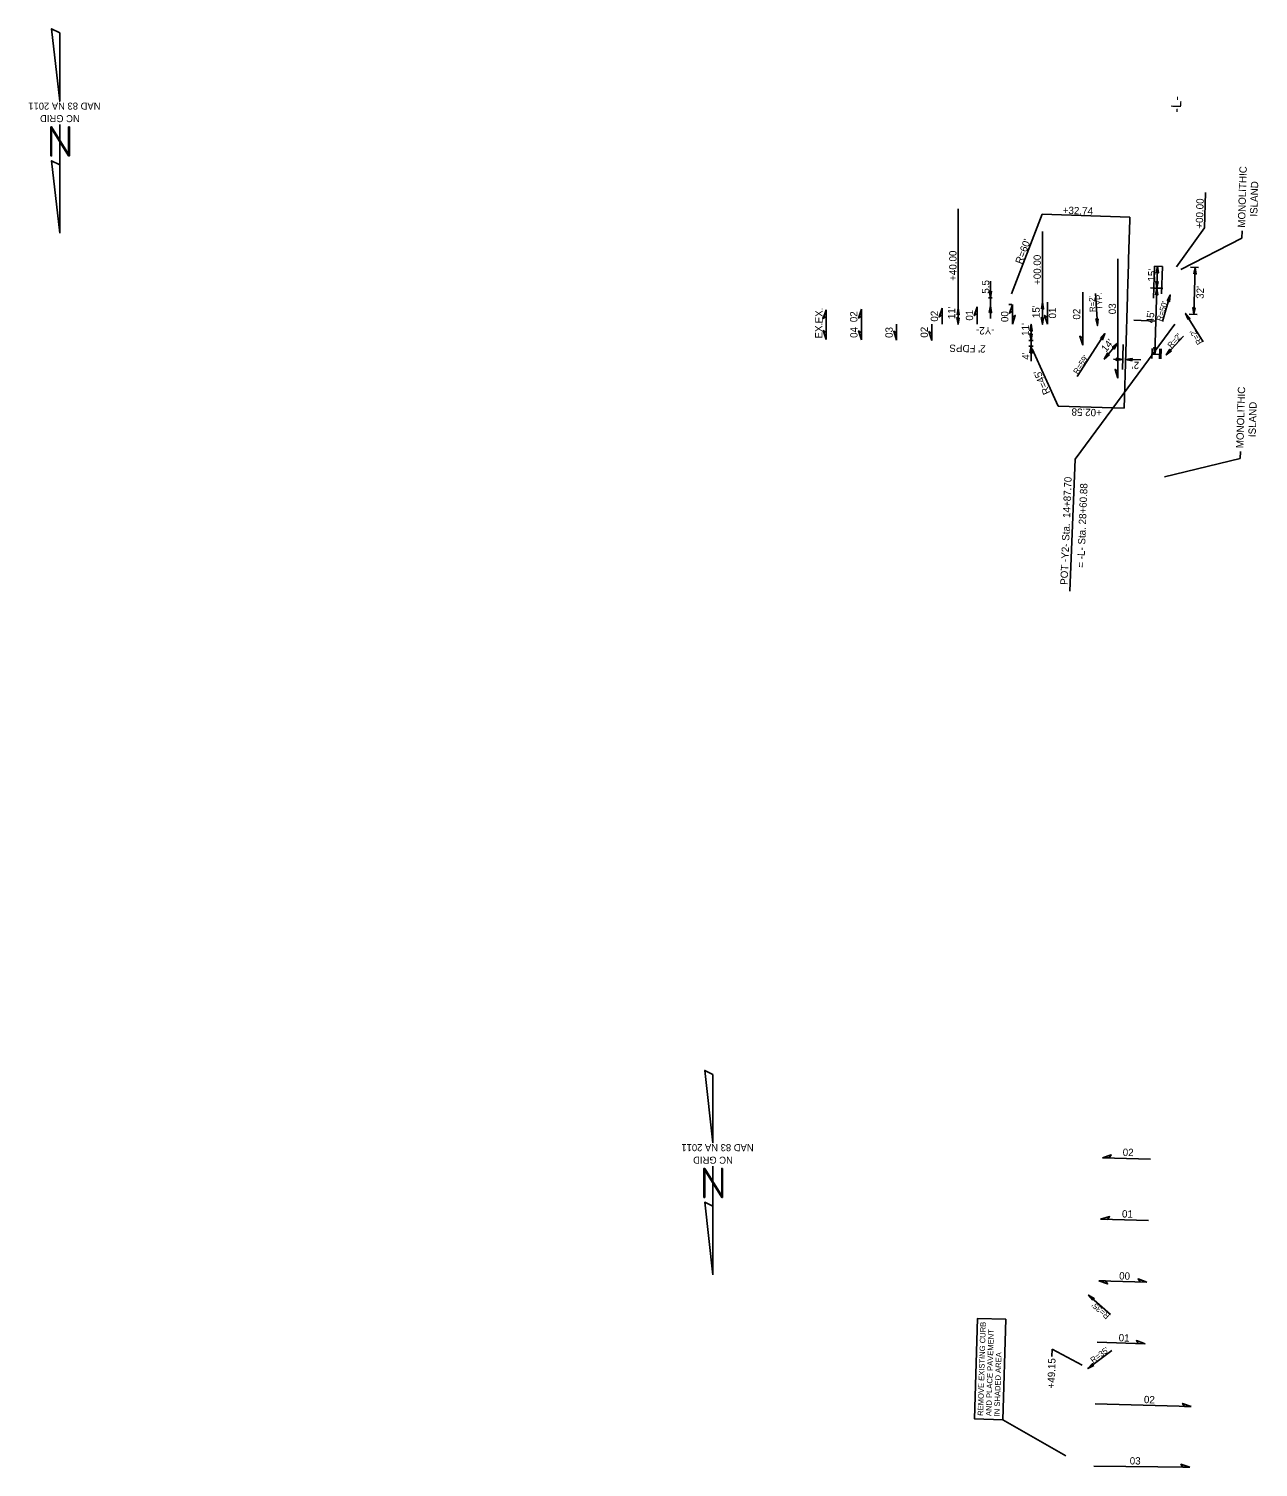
# Model space of a CAD drawing. Extents: x 2096941 to 2098098, y 685096 to 689626.
# Drawn here: x 2096941 to 2097780, y 686100 to 687081 of the extents above; entities that cross this region are included whole.
import ezdxf

# ---------------------------------------------------------------- set-up
doc = ezdxf.new("R2010")
doc.units = 0
for name, color, linetype in [('Default', 7, 'Continuous'), ('Prop Dimension', 7, 'Continuous'), ('Prop Dimension Text', 7, 'Continuous'), ('Prop Horizontal Alignment Direction Label', 7, 'Continuous'), ('Prop Horizontal Alignment Station Label', 7, 'Continuous'), ('Prop Lane Lines', 7, 'Continuous'), ('Prop Superelevation  Arrow CELL', 7, 'Continuous'), ('Prop Superelevation Label', 7, 'Continuous'), ('Prop Terminator CELL', 7, 'Continuous'), ('Scratch_Level_3', 7, 'Continuous')]:
    doc.layers.add(name, color=color, linetype=linetype)

msp = doc.modelspace()

# ---------------------------------------------------------------- linework, layer by layer
at = {"layer": 'Default'}
for p, q in [((2096961.91, 687011.63), (2096961.91, 687011.63)), ((2097407.47, 686301.09), (2097407.47, 686301.09))]:
    msp.add_line(p, q, dxfattribs=at)
for points in [[(2096962.03, 687078.47), (2096956.53, 687081.2), (2096962.03, 687031.81)], [(2096968.61, 687014.24), (2096968.06, 687014.24), (2096968.06, 686995.58), (2096956.53, 687014.24), (2096955.98, 687014.24), (2096955.98, 686994.49), (2096956.53, 686994.49), (2096956.53, 687013.15), (2096968.06, 686994.49), (2096968.61, 686994.49)], [(2096962.03, 686941.8), (2096962.03, 686988.46), (2096956.53, 686991.21)], [(2097407.59, 686367.93), (2097402.09, 686370.66), (2097407.59, 686321.27)], [(2097414.17, 686303.7), (2097413.62, 686303.7), (2097413.62, 686285.04), (2097402.09, 686303.7), (2097401.54, 686303.7), (2097401.54, 686283.95), (2097402.09, 686283.95), (2097402.09, 686302.61), (2097413.62, 686283.95), (2097414.17, 686283.95)], [(2097407.59, 686231.26), (2097407.59, 686277.92), (2097402.09, 686280.67)]]:
    msp.add_lwpolyline(points, close=True, dxfattribs=at)
for points in [[(2096962.03, 686988.46), (2096962.03, 687015.9)], [(2097407.59, 686277.92), (2097407.59, 686305.36)]]:
    msp.add_lwpolyline(points, dxfattribs=at)
at = {"layer": 'Prop Dimension'}
for p, q in [((2097743.02, 686945.33), (2097743.72, 686969.49)), ((2097632.18, 686954.62), (2097611.37, 686900.49)), ((2097692.15, 686952.6), (2097632.18, 686954.62)), ((2097723.82, 686918.76), (2097743.02, 686945.33)), ((2097726.93, 686917), (2097768.51, 686938.38)), ((2097768.51, 686938.38), (2097768.66, 686943.38)), ((2097574.92, 686933.26), (2097574.93, 686897.34)), ((2097632.46, 686930.52), (2097632.47, 686894.61)), ((2097714.33, 686919.12), (2097709, 686919.28)), ((2097710.41, 686904.27), (2097710.84, 686919.22)), ((2097733.37, 686918.52), (2097738.92, 686918.36)), ((2097735.76, 686886.46), (2097736.69, 686918.43)), ((2097596.95, 686909.04), (2097596.96, 686883.63)), ((2097598.15, 686897.7), (2097595.73, 686897.7)), ((2097669.91, 686879.42), (2097668.74, 686900.67)), ((2097713.75, 686904.14), (2097708.43, 686904.35)), ((2097709.1, 686859.23), (2097710.41, 686904.27)), ((2097714.3, 686881.62), (2097719.66, 686899.59)), ((2097574.93, 686890.62), (2097574.93, 686879.62)), ((2097611.64, 686893.05), (2097609.43, 686893.05)), ((2097632.49, 686894.5), (2097632.49, 686879.47)), ((2097742.16, 686867.66), (2097730.11, 686887.07)), ((2097732.44, 686886.55), (2097737.99, 686886.39)), ((2097624.68, 686879.63), (2097624.69, 686854.52)), ((2097626.05, 686868.63), (2097623.09, 686868.63)), ((2097656.07, 686843.89), (2097675.12, 686873.29)), ((2097683.59, 686866.69), (2097674.64, 686855.92)), ((2097687, 686848.84), (2097687.49, 686865.8)), ((2097717.4, 686859.21), (2097728.78, 686871.61)), ((2097626.05, 686864.63), (2097623.09, 686864.63)), ((2097643.25, 686823.64), (2097625.51, 686862.81)), ((2097712.49, 686859.1), (2097707.16, 686859.3)), ((2097687.2, 686855.65), (2097680.86, 686855.83)), ((2097689.2, 686855.59), (2097699.56, 686855.29)), ((2097688.23, 686822.33), (2097643.25, 686823.64)), ((2097715.63, 686775.44), (2097767.4, 686787.94)), ((2097767.4, 686787.94), (2097767.55, 686792.93)), ((2097678.91, 686204.1), (2097663.91, 686217.37)), ((2097639.03, 686180.49), (2097638.88, 686175.54)), ((2097659.54, 686169.46), (2097639.03, 686180.49)), ((2097679.8, 686179.46), (2097663.51, 686167.26)), ((2097648.5, 686107.59), (2097605.42, 686132.29))]:
    msp.add_line(p, q, dxfattribs=at)
msp.add_lwpolyline([(2097605.42, 686132.29), (2097607.41, 686200.83), (2097588.16, 686201.39), (2097586.16, 686132.85)], close=True, dxfattribs=at)
at = {"layer": 'Prop Horizontal Alignment Station Label'}
for p in [(2097722.66, 686879.66), (2097651.23, 686697.48)]:
    msp.add_line(p, (2097654.68, 686787.58), dxfattribs=at)
at = {"layer": 'Prop Lane Lines'}
msp.add_line((2097688.23, 686822.33), (2097690.45, 686898.74), dxfattribs=at)
msp.add_arc((2108718.54, 686578.14), 11032.75, 178.054987, 178.33483, dxfattribs=at)
at = {"layer": 'Prop Superelevation  Arrow CELL'}
for p, q in [((2097683.95, 686842.83), (2097683.93, 686924.26)), ((2097659.94, 686865.43), (2097659.93, 686901.44)), ((2097484.96, 686879.59), (2097484.96, 686889.56)), ((2097508.96, 686879.6), (2097508.96, 686889.9)), ((2097563.94, 686879.61), (2097563.94, 686890.61)), ((2097587.94, 686879.62), (2097587.94, 686891.5)), ((2097611.94, 686879.63), (2097611.94, 686893.13)), ((2097635.94, 686879.63), (2097635.93, 686894.75)), ((2097484.96, 686869.28), (2097484.96, 686879.59)), ((2097508.96, 686869.07), (2097508.96, 686879.6)), ((2097532.96, 686868.85), (2097532.96, 686879.61)), ((2097556.96, 686868.64), (2097556.96, 686879.61)), ((2097673.37, 686311.09), (2097706.1, 686310.14)), ((2097672.15, 686269.11), (2097704.88, 686268.15)), ((2097670.93, 686227.12), (2097703.66, 686226.17)), ((2097669.7, 686185.14), (2097702.44, 686184.19)), ((2097668.48, 686143.16), (2097733.96, 686141.26)), ((2097667.39, 686100.53), (2097732.89, 686099.91))]:
    msp.add_line(p, q, dxfattribs=at)
for points in [[(2097484.96, 686889.56), (2097482.96, 686883.56), (2097484.96, 686884.93)], [(2097508.96, 686889.9), (2097506.96, 686883.89), (2097508.96, 686885.27)], [(2097563.94, 686890.61), (2097561.94, 686884.61), (2097563.94, 686885.99)], [(2097587.94, 686891.5), (2097585.94, 686885.5), (2097587.94, 686886.88)], [(2097611.94, 686893.13), (2097609.94, 686887.13), (2097611.94, 686888.51)], [(2097611.94, 686879.63), (2097613.94, 686885.63), (2097611.94, 686884.25)], [(2097635.94, 686879.63), (2097633.94, 686885.63), (2097635.94, 686884.26)], [(2097484.96, 686869.28), (2097482.96, 686875.28), (2097484.96, 686873.91)], [(2097508.96, 686869.07), (2097506.96, 686875.07), (2097508.96, 686873.69)], [(2097532.96, 686868.85), (2097530.96, 686874.85), (2097532.96, 686873.48)], [(2097556.96, 686868.64), (2097554.96, 686874.64), (2097556.96, 686873.27)], [(2097659.94, 686865.43), (2097657.94, 686871.42), (2097659.94, 686870.05)], [(2097683.95, 686842.83), (2097681.95, 686848.83), (2097683.95, 686847.45)], [(2097673.37, 686311.09), (2097679.42, 686312.91), (2097677.99, 686310.95)], [(2097672.15, 686269.11), (2097678.2, 686270.93), (2097676.77, 686268.97)], [(2097703.66, 686226.17), (2097697.72, 686228.35), (2097699.04, 686226.31)], [(2097670.93, 686227.12), (2097676.86, 686224.95), (2097675.55, 686226.99)], [(2097702.44, 686184.19), (2097696.5, 686186.36), (2097697.82, 686184.32)], [(2097733.96, 686141.26), (2097728.02, 686143.43), (2097729.33, 686141.39)], [(2097732.89, 686099.91), (2097726.9, 686101.97), (2097728.26, 686099.95)]]:
    msp.add_lwpolyline(points, close=True, dxfattribs=at)
at = {"layer": 'Prop Terminator CELL'}
for points in [[(2097709.94, 686914.75), (2097710.84, 686919.22), (2097711.51, 686914.68), (2097710.73, 686915.28)], [(2097735.78, 686913.95), (2097736.69, 686918.43), (2097737.36, 686913.88), (2097736.57, 686914.48)], [(2097711.3, 686908.71), (2097710.41, 686904.27), (2097709.74, 686908.78), (2097710.52, 686908.19)], [(2097597.73, 686902.2), (2097596.96, 686897.7), (2097596.15, 686902.22), (2097596.96, 686901.65)], [(2097709.49, 686899.76), (2097710.41, 686904.27), (2097711.08, 686899.69), (2097710.29, 686900.29)], [(2097717.63, 686895.5), (2097719.66, 686899.59), (2097719.13, 686895.03), (2097718.53, 686895.81)], [(2097574.16, 686886.12), (2097574.93, 686890.62), (2097575.73, 686886.09), (2097574.93, 686886.67)], [(2097596.18, 686887.61), (2097596.96, 686892.12), (2097597.76, 686887.59), (2097596.96, 686888.17)], [(2097631.69, 686890.17), (2097632.46, 686894.67), (2097633.26, 686890.14), (2097632.46, 686890.72)], [(2097731.82, 686882.84), (2097730.11, 686887.07), (2097733.17, 686883.65), (2097732.19, 686883.71)], [(2097736.66, 686890.93), (2097735.76, 686886.46), (2097735.09, 686891), (2097735.87, 686890.4)], [(2097575.71, 686884.12), (2097574.93, 686879.62), (2097574.13, 686884.14), (2097574.93, 686883.57)], [(2097623.91, 686875.13), (2097624.68, 686879.63), (2097625.49, 686875.11), (2097624.69, 686875.68)], [(2097633.24, 686884.13), (2097632.47, 686879.63), (2097631.67, 686884.16), (2097632.47, 686883.58)], [(2097670.47, 686883.3), (2097669.95, 686878.76), (2097668.9, 686883.24), (2097669.73, 686882.71)], [(2097625.46, 686873.13), (2097624.69, 686868.63), (2097623.89, 686873.16), (2097624.69, 686872.58)], [(2097672.02, 686869.93), (2097675.12, 686873.29), (2097673.33, 686869.06), (2097672.97, 686869.97)], [(2097680.11, 686863.73), (2097683.59, 686866.69), (2097681.31, 686862.7), (2097681.06, 686863.65)], [(2097623.91, 686860.13), (2097624.69, 686864.63), (2097625.49, 686860.11), (2097624.69, 686860.68)], [(2097678.11, 686858.89), (2097674.64, 686855.92), (2097676.92, 686859.92), (2097677.16, 686858.96)], [(2097682.72, 686856.55), (2097687.2, 686855.65), (2097682.65, 686854.98), (2097683.25, 686855.76)], [(2097693.67, 686854.69), (2097689.2, 686855.59), (2097693.74, 686856.26), (2097693.14, 686855.48)], [(2097710, 686863.7), (2097709.1, 686859.23), (2097708.43, 686863.77), (2097709.21, 686863.17)], [(2097720.56, 686861.51), (2097716.95, 686858.72), (2097719.42, 686862.6), (2097719.62, 686861.63)], [(2097666.77, 686213.81), (2097663.91, 686217.37), (2097667.83, 686214.97), (2097666.87, 686214.76)], [(2097667.57, 686169.34), (2097663.51, 686167.26), (2097666.65, 686170.62), (2097666.67, 686169.63)]]:
    msp.add_lwpolyline(points, close=True, dxfattribs=at)
at = {"layer": 'Scratch_Level_3'}
for p, q in [((2097709, 686919.28), (2097708.16, 686897.32)), ((2097714.33, 686919.12), (2097713.61, 686900.33)), ((2097714.62, 686904.11), (2097706.24, 686904.43)), ((2097709.75, 686881.73), (2097694.68, 686882.31)), ((2097707.04, 686856.32), (2097707.3, 686863.02)), ((2097712.37, 686856.11), (2097712.63, 686862.82)), ((2097713.22, 686856.08), (2097713.48, 686862.79))]:
    msp.add_line(p, q, dxfattribs=at)
for points in [[(2097574.93, 686879.62), (2097574.93, 686890.62), (2097574.91, 686958.26)], [(2097632.46, 686885.61), (2097632.46, 686894.67), (2097632.45, 686942.93)]]:
    msp.add_lwpolyline(points, dxfattribs=at)

# ---------------------------------------------------------------- texts
at = {"layer": 'Default'}
for s, p in [('NAD 83 NA 2011', (2096989.84, 687030.85)), ('NC GRID', (2096975.69, 687022.3)), ('NAD 83 NA 2011', (2097435.4, 686320.31)), ('NC GRID', (2097421.25, 686311.76))]:
    msp.add_text(s, height=4.8, rotation=180, dxfattribs=at).set_placement(p)
at = {"layer": 'Prop Dimension Text'}
for s, height, rotation, p in [('MONOLITHIC', 5, 88.33483, (2097770.66, 686945.45)), ('ISLAND', 5, 88.33483, (2097779.01, 686953)), ('+00.00', 5, 88.33483, (2097741.9, 686944.77)), ('+32.74', 5, 357.96297, (2097646.22, 686955)), ("R=60'", 5, 68.97784, (2097618.34, 686920.27)), ('+40.00', 5, 90.01603, (2097573.83, 686909.25)), ('+00.00', 5, 90.01603, (2097631.37, 686906.43)), ("15'", 5, 88.33483, (2097709.38, 686908.67)), ('5.5', 5, 90.01603, (2097596.13, 686900.48)), ("32'", 5, 88.33483, (2097742.42, 686896.91)), ("R=2'", 4, 93.15522, (2097668.68, 686888.07)), ('TYP.', 4, 93.15522, (2097673.47, 686889.55)), ("R=50'", 4, 73.41673, (2097713.99, 686881.35)), ("11'", 5, 90.01603, (2097572.97, 686883.12)), ("15'", 5, 90.01603, (2097630.61, 686883.82)), ("45'", 5, 88.33483, (2097708.51, 686880.19)), ("11'", 5, 90.01603, (2097623.32, 686871.69)), ("2' FDPS", 5, 178.63937, (2097593.72, 686865.22)), ("14'", 5, 50.28205, (2097675.8, 686860.3)), ("R=2'", 4, 47.45626, (2097720.28, 686863.05)), ("R=2'", 4, 121.83734, (2097741.81, 686867.23)), ("4'", 5, 90.01603, (2097623.6, 686855.41)), ("R=59'", 4, 57.06634, (2097656.46, 686845.17)), ("R=45'", 5, 114.35668, (2097637.92, 686832.98)), ("2'", 5, 178.33483, (2097698.51, 686853.99)), ('MONOLITHIC', 5, 88.33483, (2097769.55, 686795)), ('+02.58', 5, 178.33483, (2097673.01, 686821.71)), ('ISLAND', 5, 88.33483, (2097777.9, 686802.56)), ("R=35'", 4, 138.51114, (2097678.7, 686203.59)), ('REMOVE EXISTING CURB', 3.75, 88.33483, (2097591.97, 686134.93)), ('AND PLACE PAVEMENT', 3.75, 88.33483, (2097597.59, 686134.76)), ("R=35'", 4, 36.82444, (2097667, 686170.7)), ('IN SHADED AREA', 3.75, 88.33483, (2097603.22, 686134.6)), ('+49.15', 5, 88.33483, (2097640.8, 686153.61))]:
    msp.add_text(s, height=height, rotation=rotation, dxfattribs=at).set_placement(p)
at = {"layer": 'Prop Horizontal Alignment Direction Label'}
for s, height, rotation, p in [('-L-', 7, 87.8037, (2097726.9, 687023.85)), ('-Y2-', 5, 180.01603, (2097599.78, 686877.66))]:
    msp.add_text(s, height=height, rotation=rotation, dxfattribs=at).set_placement(p)
at = {"layer": 'Prop Horizontal Alignment Station Label'}
for s, p in [('POT -Y2- Sta.  14+87.70', (2097649.58, 686701.77)), ('= -L- Sta. 28+60.88', (2097661.01, 686713.48))]:
    msp.add_text(s, height=5, rotation=87.8037, dxfattribs=at).set_placement(p)
at = {"layer": 'Prop Superelevation Label'}
for s, rotation, p in [('EX.', 90.01603, (2097482.5, 686880.2)), ('02', 90.01603, (2097506.21, 686881.03)), ('02', 90.01603, (2097561.24, 686881.41)), ('01', 90.01603, (2097585.17, 686882.11)), ('00', 90.01603, (2097609.17, 686881.12)), ('01', 90.01603, (2097641.75, 686883.57)), ('02', 90.01603, (2097658.24, 686882.81)), ('03', 90.01603, (2097682.62, 686886.44)), ('EX.', 90.01603, (2097482.35, 686869.88)), ('04', 90.01603, (2097506.3, 686870.32)), ('03', 90.01603, (2097530.3, 686870.3)), ('02', 90.01603, (2097554.3, 686870.47)), ('02', 358.25016, (2097687.14, 686312.32)), ('01', 358.25016, (2097686.64, 686270.31)), ('00', 358.25016, (2097684.71, 686228.02)), ('01', 358.25016, (2097684.4, 686185.8)), ('02', 358.25016, (2097701.61, 686143.66)), ('03', 359.37182, (2097691.97, 686101.82))]:
    msp.add_text(s, height=5, rotation=rotation, dxfattribs=at).set_placement(p)

doc.saveas('drawing.dxf')
